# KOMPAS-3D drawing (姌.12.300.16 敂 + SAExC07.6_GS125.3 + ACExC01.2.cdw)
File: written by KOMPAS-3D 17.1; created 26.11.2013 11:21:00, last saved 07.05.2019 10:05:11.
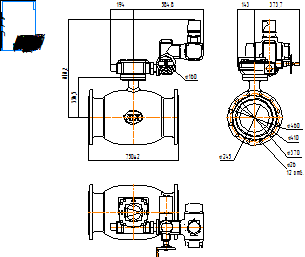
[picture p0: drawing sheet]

Sheet 1: A3, portrait

Title block, sheet 1: name: КШ.12.300.16 ФФ + / SAExC07.6_GS125.3 + ACExC01.2; material: Внимание! Данный продукт является объектом авторского права ООО «Торговый Дом АДЛ». / Запрещается изменение, копирование, распространение / (в том числе путем копирования на другие сайты и ресурсы в Интернете) / или любое иное использование информации и объектов без предварительного / согласия правообладателя (ООО «Торговый Дом АДЛ»).; scale: 1:5; sheets: 1; organisation: ООО "Торговый дом АДЛ"; sheet format: A3; stored path: C:\Users\kka\Desktop\Альбом БИВАЛ\1 Ду150 Полнопроходной сварка-сварка на опоре с приводом SG12.1\КШТ 14.150.25 СС + SG12.1 альбом стр.1.cdw; drawn by: Климкович К.А.; drawn by, date: 05.02.16

Views: Спереди 2, Проекционный вид 3, Проекционный вид 4
Referenced files in C:\Users\kka\KOMPAS_Work\Модели кранов для исследований\DN300\: АПТА.0203-1352.00.00-01 _ Кран шаровой сварной Ду300.a3d, АПТА.0203-1352.00.00-01 _ Кран шаровой сварной Ду300.a3d!АПТА.0203-1352.00.00!Деталь (локальная) 2.m3d, Фланец 1-300-16 Ст.20 ГОСТ 12820-80.m3d, АПТА.0203-1352.00.00-01 _ Кран шаровой сварной Ду300.a3d!АПТА.0203-1352.00.00!Деталь (локальная) 3.m3d
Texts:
  Klimkovich
  ADL
  K5LT_THIN_RGB_0_0_0_THICK_0.18
  K5LT_AXLED_RGB_255_128_0_SC_1_THICK_0.18
Dimensions and other numbers on the sheet: 336,5; 750±2; 818,2; 194; 584,8; 160; 245; 410; 460; 370; 26; 12 отв.; 373,7; 143; 1:5; 1; 05.02.16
